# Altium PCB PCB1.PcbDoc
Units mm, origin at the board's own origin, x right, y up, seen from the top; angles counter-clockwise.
Board outline 30.4 x 31.22 mm, 2 copper layers (Top Layer, Bottom Layer); 47 components, 33 nets, 158 pads, 154 vias.
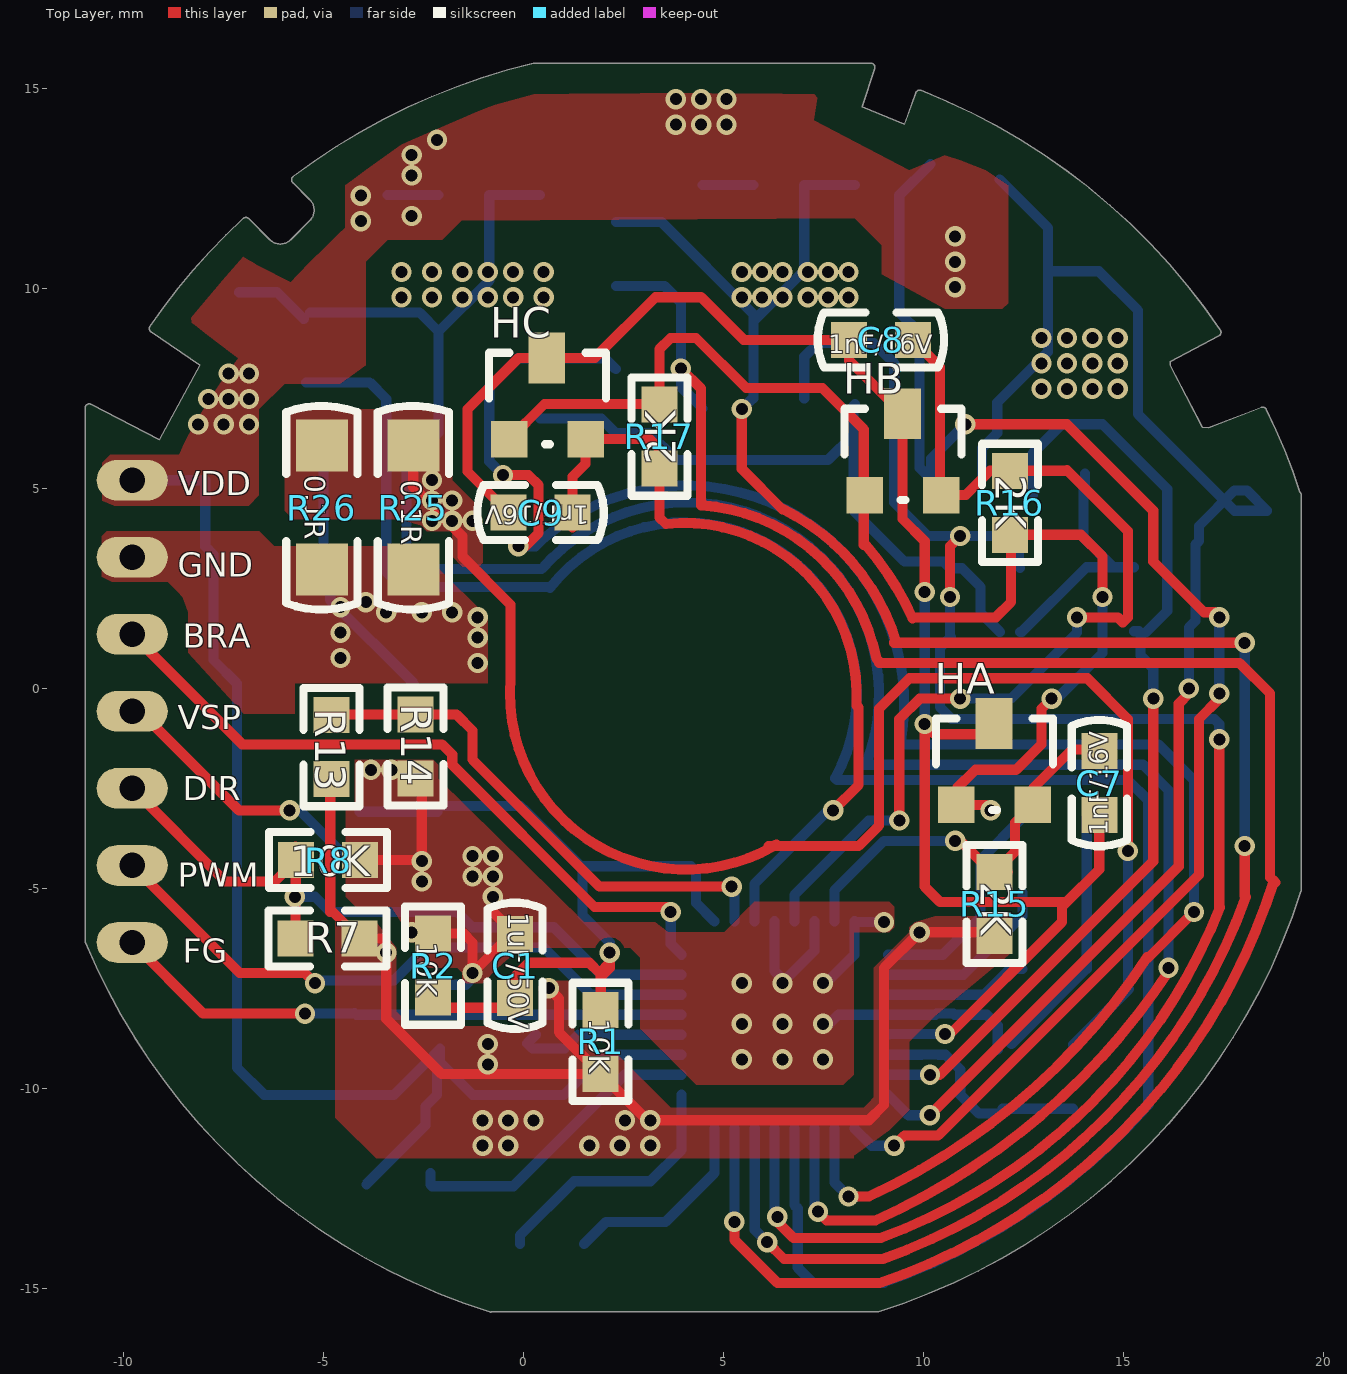
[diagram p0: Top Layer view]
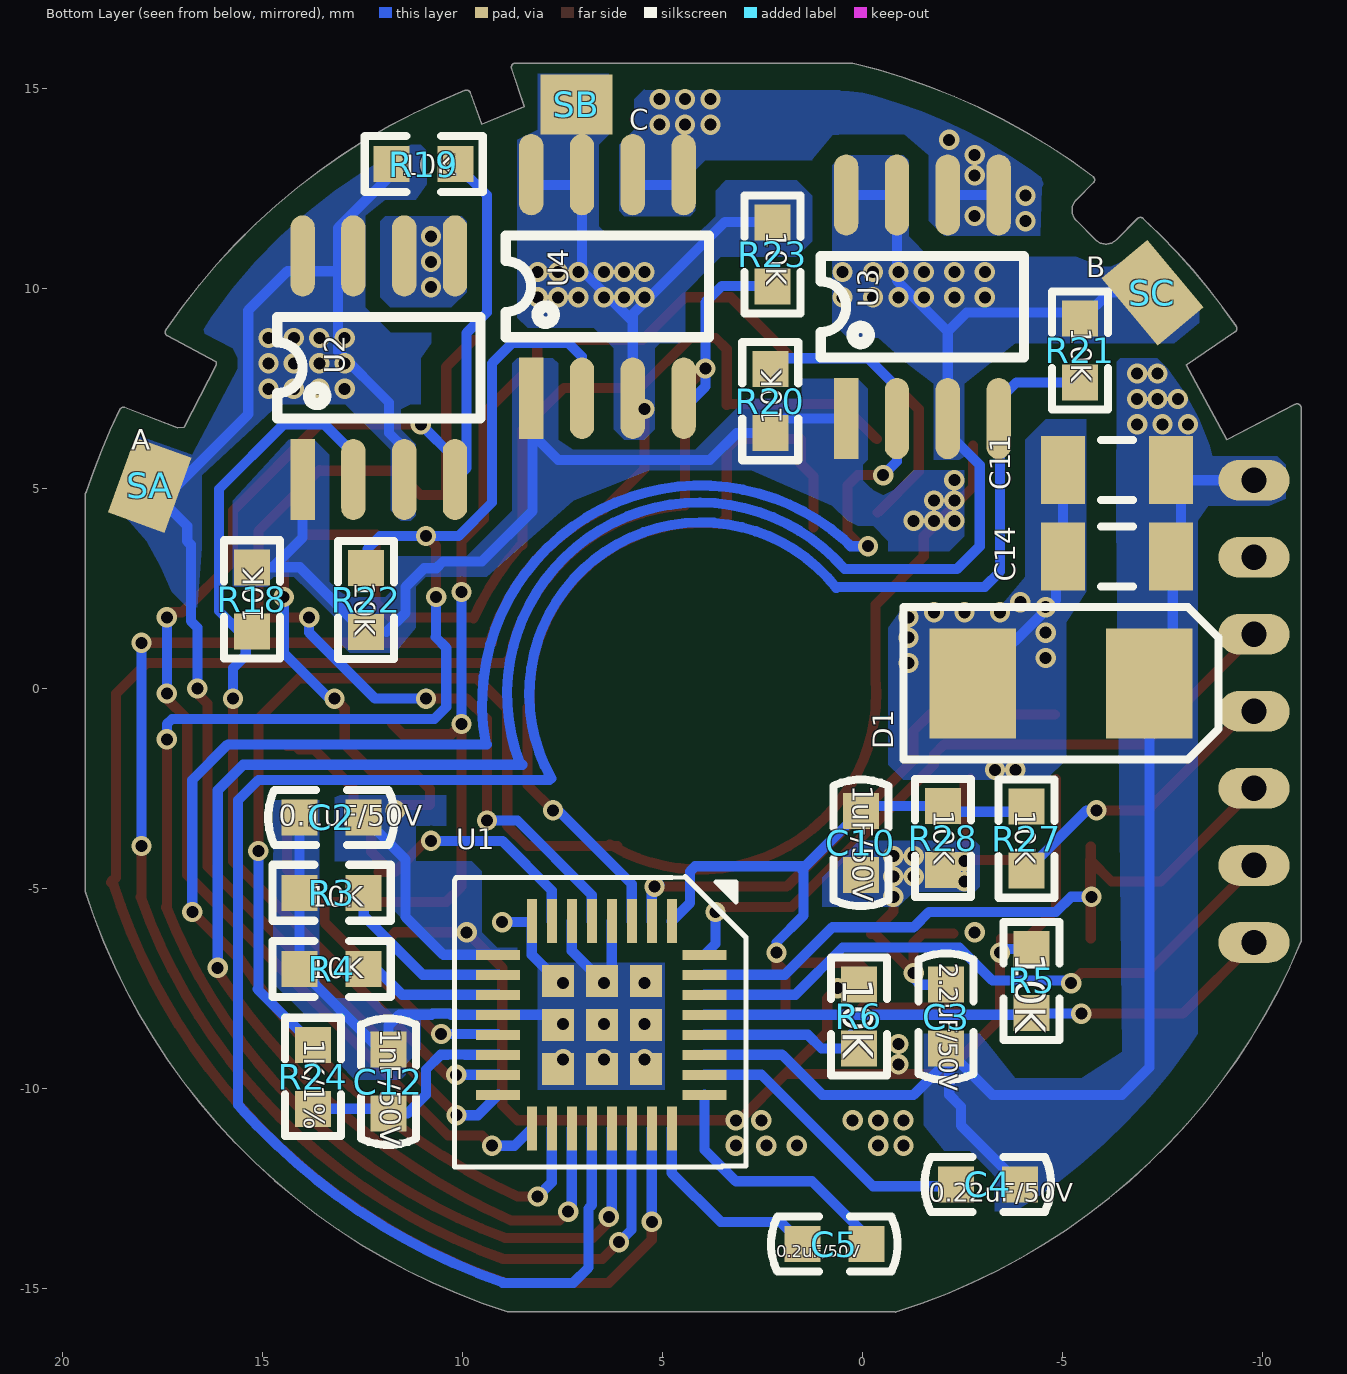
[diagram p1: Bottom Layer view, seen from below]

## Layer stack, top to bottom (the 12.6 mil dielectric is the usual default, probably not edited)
Top Solder: solder mask 0.0102, Solder Resist, Dk 3.5
Top Layer: signal copper 0.0356
Dielectric 1: dielectric 0.32, FR-4, Dk 4.8
Bottom Layer: signal copper 0.0356
Bottom Solder: solder mask 0.0102, Solder Resist, Dk 3.5

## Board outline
-10.95,-6.341 cw(c-10.855,-6.302) -10.957,-6.302 -10.957,7.013 cw(c-10.855,7.013) -10.808,7.104 -10.809,7.104 -10.808,7.104 -9.097,6.22 -8.084,8.083 -9.308,8.915 cw(c-9.251,8.999) -9.335,9.057 cw(c4.013,-0.127) -7.007,11.75 cw(c-6.938,11.675) -6.86,11.741 -6.338,11.219 ccw(c-6.41,11.147) -6.338,11.219 ccw(c-6.077,11.479) -5.817,11.219 -5.338,11.698 ccw(c-5.266,11.626) -5.338,11.698 ccw(c-5.598,11.958) -5.23,11.958 ccw(c-5.598,11.958) -5.338,12.218 cw(c-5.266,12.291) -5.338,12.219 -5.338,12.218 -5.765,12.646 cw(c-5.693,12.718) -5.755,12.799 cw(c4.013,-0.127) 0.255,15.633 cw(c0.279,15.534) 0.298,15.634 8.687,15.634 cw(c8.687,15.532) 8.789,15.532 cw(c8.687,15.532) 8.784,15.5 8.47,14.548 9.529,14.106 9.809,14.89 cw(c9.905,14.856) 9.943,14.951 cw(c4.013,-0.127) 17.425,8.964 cw(c17.34,8.906) 17.442,8.906 cw(c17.34,8.906) 17.388,8.816 16.167,8.168 16.167,8.089 16.969,6.535 17.131,6.517 18.447,7.025 cw(c18.484,6.93) 18.576,6.975 cw(c4.013,-0.127) 19.413,4.908 cw(c19.343,4.834) 19.445,4.834 19.445,-5.047 ccw(c19.343,-5.047) 19.445,-5.045 19.445,-5.047 cw(c19.343,-5.047) 19.44,-5.078 cw(c4.013,-0.127) 8.881,-15.58 cw(c8.85,-15.483) 8.85,-15.585 -0.789,-15.585 cw(c-0.814,-15.486) -0.844,-15.584 cw(c4.013,-0.127)

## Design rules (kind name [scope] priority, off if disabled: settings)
Clearance [All] p1: gap=0.127
PolygonConnect [All] p1: connectstyle=Direct reliefconductorwidth=0.254 reliefentries=4 polygonreliefangle="90 Angle" airgapwidth=0.254
RoutingVias [All] p1: holewidth=0.711 width=1.27 viastyle="Through Hole" minholewidth=0.711 minwidth=1.27 maxholewidth=0.711 maxwidth=1.27
SilkToSilkClearance [All] p1: silktosilkclearance=0.051
SolderMaskExpansion [All] p1: expansion=0.102
Width [All] p1: maxlimit=0.254 minlimit=0.254 preferedwidth=0.254
29 further rules are at their usual default settings.

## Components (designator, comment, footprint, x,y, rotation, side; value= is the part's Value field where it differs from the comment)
C1 "1uF/50V" C0603 -3.302,-7.239 r180 top
C2 "0.1uF/50V" C0603 13.589,-0.127 r90 bottom
C3 "2.2uF/50V" C0603 1.016,-8.509 r0 bottom
C4 "0.22uF/50V" C0603 -3.429,-15.494 r270 bottom
C5 "0.2uF/50V" C0603 1.016,-10.795 r90 bottom
C7 "1nF/16V" C0603 11.303,-2.667 r180 top
C8 "1nF/16V" C0603 8.636,11.811 r90 top
C9 "1nF/16V" C0603 0.127,7.493 r90 top
C10 "1uF/50V" C0603 -3.048,-3.556 r180 bottom
C11 "22uF/25V" C1206 -6.35,5.461 r180 bottom
C12 "1nF/50V" C0603 8.763,-9.525 r180 bottom
C14 "22uF/25V" C1206 -6.35,3.302 r180 bottom
D1 "24V/Zener" SMB -4.953,0.127 r180 bottom
HA "HALL_SOT23-3" SOT-23 15.113,-2.54 r0 top locked
HB "HALL_SOT23-3" SOT-23 12.827,5.207 r0 top locked
HC "HALL_SOT23-3" SOT-23 3.937,6.604 r0 top locked
R1 "10K" R0603 0.254,-10.287 r180 top
R2 "10K" R0603 -3.937,-8.382 r180 top
R3 "10K" R0603 14.732,-3.429 r90 bottom
R4 "10K" R0603 14.732,-5.334 r90 bottom
R5 "10K" R0603 -2.54,-8.763 r0 bottom
R6 "10K" R0603 1.778,-9.652 r0 bottom
R7 "" R0603 -6.35,-4.572 r90 top
R8 "10K" R0603 -3.429,-5.969 r270 top
R13 "" R0603 -6.477,-2.921 r180 top
R14 "" R0603 -1.016,0 r0 top
R15 "2K" R0603 13.462,-3.937 r0 top
R16 "2K" R0603 13.843,6.096 r0 top
R17 "2K" R0603 5.08,7.747 r0 top
R18 "10K" R0603 13.589,3.683 r180 bottom
R19 "10K" R0603 9.525,11.43 r270 bottom
R20 "10K" R0603 0.635,8.636 r180 bottom
R21 "10K" R0603 -7.112,9.906 r180 bottom
R22 "10K" R0603 14.097,0.762 r0 bottom
R23 "10K" R0603 3.937,9.398 r0 bottom
R24 "1K/1%" R0603 12.065,-8.255 r180 bottom
R25 "0.1R" R1206 -0.508,4.445 r0 top
R26 "0.1R" R1206 -2.794,4.445 r0 top
R27 "10K" R0603 -2.413,-5.207 r0 bottom
R28 "10K" R0603 -3.683,-2.286 r180 bottom
SA "" cp1#1 23.749,7.239 r20 top
SB "" cp1#2 13.462,14.605 r0 top
SC "" cp1#3 -2.413,5.842 r320 top
U1 "SDC9270_QFN32" "QFN32 (5*5)" 6.604,-3.175 r270 bottom
U2 "MOS" SOP-8 17.907,7.874 r0 bottom
U3 "MOS" SOP-8 4.318,9.398 r0 bottom
U4 "MOS" SOP-8 12.192,9.906 r0 bottom

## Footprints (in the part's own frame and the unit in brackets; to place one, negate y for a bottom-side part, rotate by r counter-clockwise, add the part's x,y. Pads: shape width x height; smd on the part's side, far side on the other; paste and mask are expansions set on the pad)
C0603 [mm]
  rect 0.9x0.9 smd: 1(-3.096,0.496) 2(-3.096,-1.104)
  silkscreen extent -3.78,-1.88 -2.41,1.28
C1206 [mm] "Chip Capacitor, Body 3.2x1.6mm, IPC High Density"
  rect 1.1x1.7 smd: 1(-1.35,0) 2(1.35,0)
  silkscreen extent -0.4,-0.75 0.4,0.75, body extent -1.7,-0.9 1.7,0.9, height 1.3
cp1#1 [mm]
  rect 1.5x2 smd far side: 1(-6.3,0)
cp1#2 [mm]
  rect 1.8x1.5 smd far side: 1(-6.3,0)
cp1#3 [mm]
  rect 1.5x2.2 smd far side: 1(-6.3,0)
"QFN32 (5*5)" [mm]
  rect 1.1x0.25 smd: 1(2.643,1.828) 2(2.643,1.328) 3(2.643,0.828) 4(2.643,0.328) 5(2.643,-0.172) 6(2.643,-0.672) 7(2.643,-1.172) 8(2.643,-1.672) 17(7.823,-1.672) 18(7.823,-1.172) 19(7.823,-0.672) 20(7.823,-0.172) 21(7.823,0.328) 22(7.823,0.828) 23(7.823,1.328) 24(7.823,1.828)
  rect 0.25x1.1 smd: 9(3.483,-2.512) 10(3.983,-2.512) 11(4.483,-2.512) 12(4.983,-2.512) 13(5.483,-2.512) 14(5.983,-2.512) 15(6.483,-2.512) 16(6.983,-2.512) 25(6.983,2.648) 26(6.483,2.648) 27(5.983,2.648) 28(5.483,2.648) 29(4.983,2.648) 30(4.483,2.648) 31(3.983,2.648) 32(3.483,2.648)
  rect 0.8x0.8 smd: 33(4.133,-1.022) 33(4.133,0.078) 33(4.133,1.178) 33(5.233,-1.022) 33(5.233,0.078) 33(5.233,1.178) 33(6.333,-1.022) 33(6.333,0.078) 33(6.333,1.178)
  silkscreen extent 1.52,-3.6 8.79,3.68
R0603 [mm]
  rect 0.9x0.9 smd: 1(-1.679,-0.653) 2(-1.679,-2.253)
  silkscreen extent -2.38,-2.93 -0.98,0.02
R1206 [mm]
  rect 1.3x1.3 smd: 1(-2.244,-1.475) 2(-2.244,1.625)
  silkscreen extent -3.13,-2.47 -1.35,2.62
SMB [mm]
  rect 2.159x2.743 smd: 1(-2.21,0) 2(2.21,0)
  silkscreen extent -3.94,-1.91 3.94,1.91
SOP-8 [mil]
  rect 24x80 smd: 1(-153.56,104.3)
  oval 24x80 smd: 2(-203.56,104.3) 3(-253.56,104.3) 4(-303.56,104.3) 5(-303.56,-115.7) 6(-253.56,-115.7) 7(-203.56,-115.7) 8(-153.56,-115.7)
  silkscreen extent -329,-56 -129,44
SOT-23 [mil]
  rect 36x36 smd: 1(-93.79,-14.61) 3(-168.79,-14.61)
  rect 36x50 smd: 2(-131.79,65.39)
  silkscreen extent -189,-20 -74,70

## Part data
C1 C7 C8 C9 C10 C11 C12 C14: library part C0603, "C0603"
C2 C4 C5: library part C0805, "C0805"
C3: library part C1206, "C1206"
D1: library part Zener_SOD-123, "Zener Diode"
R1 R2 R3 R4 R5 R6 R7 R8 R13 R14 R15 R16 R17 R24 R27 R28: library part R0603, "R0603"
R18 R19 R20 R21 R22 R23: library part R1_0603
R25 R26: library part R2512
SA SB SC: library part CON1, "Connector"

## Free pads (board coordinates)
  oval 1.778x1.016 hole 0.635: 1(-9.779,-6.35) 1(-9.779,-4.424) 1(-9.779,-2.498) 1(-9.779,-0.572) 1(-9.779,1.355) 1(-9.779,3.281) 1(-9.779,5.207)

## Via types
v1: diameter 0.508, hole 0.3, Top Layer to Bottom Layer, 154 vias

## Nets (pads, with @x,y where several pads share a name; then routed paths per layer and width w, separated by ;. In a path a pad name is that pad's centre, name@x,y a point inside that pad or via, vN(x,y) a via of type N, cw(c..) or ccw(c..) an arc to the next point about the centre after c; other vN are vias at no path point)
BRAKE: pad.1@-9.779,1.355 U1.32 | length 17.7
  Top Layer w0.254: pad.1@-9.779,1.355 -7.027,-1.397 -2.032,-1.397 -1.778,-1.651 -1.778,-1.905 1.778,-5.461 3.683,-5.461 v1(3.683,-5.588)
  Bottom Layer w0.254: v1(3.683,-5.588) 3.683,-6.385 U1.32
CP1: C5.1 U1.24 | length 5.1
  Bottom Layer w0.254: C5.1 2.068,-13.335 3.556,-13.335 4.776,-12.115 U1.24
CP2: C5.2 U1.25 | length 6.5
  Bottom Layer w0.254: C5.2 -0.088,-13.677 1.27,-12.319 3.175,-12.319 3.956,-11.538 U1.25
DIR: pad.1@-9.779,-2.498 R7.1 R8.2 U1.31 | length 19
  Top Layer w0.254: pad.1@-9.779,-2.498 -7.451,-4.826 -6.218,-4.826 R8.2@-5.697,-4.305 ; v1(-5.715,-5.207) -5.682,-5.174 R8.2 R8.2@-5.697,-4.305 ; R7.1 R8.2@-5.697,-4.305 ; R8.2@-5.697,-3.955 R8.2@-5.697,-4.305
  Bottom Layer w0.254: v1(-5.715,-5.207) -5.207,-5.207 -4.826,-5.588 -1.651,-5.588 -1.27,-5.969 0.762,-5.969 1.951,-7.158 U1.31
FG: pad.1@-9.779,-6.35 R5.1 U1.29 | length 14.5
  Top Layer w0.254: pad.1@-9.779,-6.35 -8.001,-8.128 v1(-5.461,-8.128)
  Bottom Layer w0.254: v1(-5.461,-8.128) -4.237,-8.128 R5.1 -4.171,-8.158 U1.29
GHA: R19.1 U1.17 U2.4 | length 37.6
  Top Layer w0.254: v1(9.271,-11.43) 9.525,-11.176 10.37,-11.176 16.891,-4.655 16.891,-0.762 17.399,-0.254 v1(17.399,-0.127) ; v1(11.049,6.604) 13.589,6.604 15.748,4.445 15.748,3.175 17.018,1.905 17.272,1.905 v1(17.399,1.778)
  Bottom Layer w0.254: U1.17 8.708,-11.43 v1(9.271,-11.43) ; R19.1 9.398,12.329 9.398,9.398 9.906,8.89 9.906,5.515 U2.4 10.196,5.751 v1(11.049,6.604) ; v1(17.399,-0.127) v1(17.399,1.778)
GHB: R21.2 U1.20 U3.4 | length 53
  Bottom Layer w0.254: R21.2 -3.843,7.653 -3.429,7.239 -3.429,2.921 -3.048,2.54 0.635,2.54 ; 0.664,2.517 cw(c4.039,-0.147) 7.79,-2.249 ; U1.20 6.776,-12.916 6.858,-12.998 6.858,-14.478 7.239,-14.859 9.012,-14.859 ; 7.794,-2.241 7.839,-2.286 15.113,-2.286 15.621,-2.794 15.621,-10.414 ; 9.012,-14.844 ccw(c3.891,-0.081) 15.563,-10.47
GHC: R23.1 U1.23 U4.4 | length 51
  Top Layer w0.254: v1(3.937,8.001) 4.445,7.493 4.445,4.583 ; 4.446,4.582 cw(c4.121,-0.208) 8.826,0.749 8.89,0.685 8.89,0.635 17.907,0.635 18.669,-0.127 18.669,-4.725 18.796,-4.852 ; v1(5.276,-13.335) 5.276,-13.785 6.35,-14.859 8.89,-14.859 ; 8.892,-14.865 ccw(c3.937,-0.127) 18.766,-4.803
  Bottom Layer w0.254: R23.1@2.314,10.066 3.523,10.066 3.937,9.652 v1(3.937,8.001) 3.937,7.547 U4.4@4.481,7.003 ; v1(5.276,-13.335) U1.23
GLA: R18.2 U1.15 U2.2 | length 24
  Top Layer w0.254: v1(10.166,-9.658) 10.408,-9.658 15.748,-4.318 v1(15.748,-0.254)
  Bottom Layer w0.254: U1.15 v1(10.166,-9.658) ; U2.2@12.736,4.844 12.736,5.878 13.462,6.604 14.478,6.604 16.096,4.986 16.096,1.938 R18.2@15.555,1.397 ; R18.2 R18.2@15.395,1.43 ; R18.2@15.428,1.397 15.428,0.828 15.748,0.508 v1(15.748,-0.254)
GLB: R20.1 U1.18 U3.2 | length 47.2
  Top Layer w0.254: v1(-0.508,5.334) 0.127,5.334 0.381,5.08 0.381,3.888 0.049,3.556 v1(-0.127,3.556) ; v1(8.128,-12.7) 8.636,-12.7 ccw(c1.579,2.559) 15.599,-6.719 ; 15.616,-6.736 v1(16.764,-5.588)
  Bottom Layer w0.254: v1(-0.508,5.334) -0.853,5.679 U3.2 -0.853,7.529 -0.127,8.255 2.042,8.255 R20.1 ; v1(-0.127,3.556) 0.303,3.556 0.472,3.724 cw(c4.064,-0.381) 9.437,-1.321 ; U1.18 7.776,-12.348 v1(8.128,-12.7) ; 9.398,-1.397 15.875,-1.397 16.764,-2.286 v1(16.764,-5.588)
GLC: R22.2 U1.21 U4.2 | length 44.7
  Top Layer w0.254: v1(6.35,-13.208) 6.35,-13.335 6.75,-13.735 8.944,-13.735 ccw(c3.937,-0.127) 17.417,-5.468 17.399,-5.45 v1(17.399,-1.27) ; v1(10.668,2.286) 10.668,3.556 v1(10.922,3.81)
  Bottom Layer w0.254: v1@6.276,-13.134 U1.21 ; U4.2 7.021,8.291 7.366,8.636 8.763,8.636 9.271,8.128 9.271,4.649 10.11,3.81 v1(10.922,3.81) 12.065,3.81 12.385,3.49 12.385,3.048 R22.2 ; v1(10.668,2.286) 10.668,1.303 10.684,1.286 10.414,1.016 10.414,-0.464 10.712,-0.762 17.272,-0.762 17.399,-0.889 v1(17.399,-1.27)
GND: 
HA: C9.2 HC.1 R17.2 U1.3 | length 20.5
  Top Layer w0.254: C9.2@1.231,4.025 C9.2 1.231,5.295 1.555,5.619 HC.1 3.165,6.233 3.401,5.997 R17.2 3.401,4.276 3.565,4.112 cw(c4.034,-0.162) 8.326,-0.421 8.382,-0.477 8.382,-2.413 v1(7.747,-3.048)
  Bottom Layer w0.254: U1.3 5.776,-4.887 7.747,-2.916 v1(7.747,-3.048)
HB: C8.2 HB.1 R16.1 U1.5 | length 25.7
  Top Layer w0.254: v1(9.398,-3.302) 9.398,-0.762 9.906,-0.254 v1(10.922,-0.254) ; C8.2 10.414,8.041 HB.1@10.414,4.867 ; HB.1 11.059,4.836 11.666,5.443 R16.1 13.571,5.443 13.589,5.461 15.113,3.937 15.113,1.778 14.986,1.651 14.859,1.778 v1(13.843,1.778)
  Bottom Layer w0.254: U1.5 6.776,-5.162 8.636,-3.302 v1(9.398,-3.302) ; v1@10.922,-0.127 v1(10.922,-0.254) 12.192,-0.254 13.843,1.397 v1(13.843,1.778)
HC: C7.2 HA.1 R15.1 U1.7 | length 10.5
  Top Layer w0.254: v1(10.795,-3.81) 10.922,-3.81 11.702,-4.59 R15.1@12.108,-4.59 ; R15.1 12.291,-4.082 12.291,-3.351 HA.1 12.731,-2.509 13.716,-1.524 14.097,-1.524 14.185,-1.436 C7.2@14.399,-1.436
  Bottom Layer w0.254: U1.7 7.776,-5.051 9.017,-3.81 v1(10.795,-3.81)
ILIMIT: C12.2 R24.2 U1.14 | length 5.5
  Bottom Layer w0.254: U1.14 9.948,-9.158 9.956,-9.15 10.377,-9.15 10.385,-9.158 10.555,-9.158 10.922,-9.525 10.922,-10.16 11.391,-10.629 C12.2 ; C12.2@11.979,-10.508 R24.2
ISENSE: R18.1 R20.2 R22.1 R24.1 R25.2 R26.2 U2.1 U3.1 U4.1 | length 61.1
  Top Layer w0.254: R25.2 -2.752,5.038 -1.524,3.81 -1.524,3.302 -0.319,2.097 -0.319,0.254 ccw(c4.064,-0.127) 6.265,-3.937 ccw(c4.064,-0.127) 6.328,-3.9 ; 6.135,-3.937 8.382,-3.937 8.89,-3.429 8.89,-0.508 9.652,0.254 14.097,0.254 15.113,-0.762 v1(15.113,-4.064)
  Bottom Layer w0.254: U3.1 1.948,6.749 R20.2 3.154,6.383 3.822,5.715 7.62,5.715 U4.1@8.255,6.35 ; U4.1@8.291,7.112 8.255,7.076 U4.1@8.255,6.35 ; 11.91,1.415 11.43,1.895 11.43,2.54 10.965,3.005 10.667,3.005 10.497,3.175 9.525,3.175 8.255,4.445 U4.1@8.255,6.35 ; R22.1 12.464,1.415 14.079,3.03 14.75,3.03 ; R24.1 15.136,-7.516 15.113,-7.493 v1(15.113,-4.064) ; U2.1 14.006,3.774 14.75,3.03 ; U2.1@14.043,4.88 U2.1@14.043,5.37 ; R18.1 14.75,3.03
  other v1: -2.286,4.191 -1.778,4.191 -1.27,4.191 -2.286,4.699 -1.778,4.699 -2.286,5.207
LEAD: R13.2 R14.1 U1.2 | length 13.5
  Top Layer w0.254: R13.2@-4.798,-0.653 R14.1 -1.669,-0.653 -1.27,-1.052 -1.27,-1.778 1.905,-4.953 v1(5.207,-4.953)
  Bottom Layer w0.254: v1(5.207,-4.953) 5.207,-4.87 5.163,-4.826 5.08,-4.909 5.276,-5.105 U1.2
MODE: R3.2 U1.10 | length 4.5
  Bottom Layer w0.254: U1.10 11.003,-7.158 12.479,-5.682 R3.2
NetP1_3: pad.1@-9.779,-0.572 R27.1 | length 7.3
  Top Layer w0.254: pad.1@-9.779,-0.572 -9.588,-0.572 -7.112,-3.048 v1(-5.842,-3.048)
  Bottom Layer w0.254: v1(-5.842,-3.048) -5.598,-3.048 R27.1
NFLT: R6.1 U1.28 | length 4.4
  Bottom Layer w0.254: R6.1@0.313,-8.658 0.099,-8.872 0.226,-8.999 1.034,-8.999 1.375,-8.658 U1.28
PGND: C7.1 C8.1 C9.1 HA.2 HB.2 HC.2 U1.13 | length 43
  Top Layer w0.254: C9.1 -1.397,5.425 -1.397,6.985 -0.117,8.265 HC.2 1.788,8.265 3.302,9.779 4.445,9.779 5.509,8.715 C8.1 8.14,8.208 HB.2 9.479,4.237 10.033,3.683 v1(10.033,2.413) ; v1(10.541,-8.636) 10.668,-8.636 13.462,-5.842 13.462,-5.461 13.589,-5.334 ; HA.2 11.502,-1.143 10.287,-1.143 v1(10.033,-0.889) 10.033,-4.953 10.414,-5.334 13.589,-5.334 ; C7.1@14.399,-3.036 14.399,-4.524 13.589,-5.334
  Bottom Layer w0.254: U1.13 9.138,-8.636 v1(10.541,-8.636) ; v1(10.033,-0.889) v1(10.033,2.413)
PWM: pad.1@-9.779,-4.424 U1.30 | length 15.8
  Top Layer w0.254: pad.1@-9.779,-4.445 -9.779,-4.424 -7.091,-7.112 -5.461,-7.112 v1(-5.207,-7.366)
  Bottom Layer w0.254: v1(-5.207,-7.366) -5.142,-7.301 -3.237,-7.301 -2.413,-6.477 0.508,-6.477 1.689,-7.658 U1.30
PWMIN: 
SA: R19.2 SA.1 U1.16 U2.3 U2.7 U2.8 | length 39.2
  Top Layer w0.254: v1(10.16,-10.668) 16.383,-4.445 16.383,-0.381 16.637,-0.127 v1(16.637,0)
  Bottom Layer w0.254: U1.16 9.626,-10.668 v1(10.16,-10.668) ; U2.3 11.466,6.005 11.847,6.386 11.847,7.148 13.117,8.418 13.117,10.432 ; R19.2@11.905,12.728 13.117,11.516 13.117,10.432 ; v1(16.637,0) 16.637,1.524 16.8,1.687 16.8,3.592 16.891,3.683 16.891,4.064 17.78,4.953 18.084,4.953 18.592,4.445 17.78,4.445 15.367,6.858 15.367,9.452 14.387,10.432 13.117,10.432
  other v1: 12.954,7.493 13.589,7.493 14.224,7.493 14.859,7.493 12.954,8.128 13.589,8.128 14.224,8.128 14.859,8.128 12.954,8.763 13.589,8.763 14.224,8.763 14.859,8.763
SB: R21.1 SC.1 U1.19 U3.3 U3.7 U3.8 | length 59.1
  Top Layer w0.254: v1(7.366,-13.081) 7.587,-13.302 8.798,-13.302 ccw(c1.7,2.497) v1@16.176,-7.012
  Bottom Layer w0.254: SC.1@-7.112,9.906 -6.157,9.906 R21.1@-5.489,9.238 ; R21.1@-5.329,9.398 -2.594,9.398 -2.123,8.926 ; U3.8 U3.7 -0.853,10.196 -2.123,8.926 ; U1.19 7.276,-12.991 v1(7.366,-13.081) ; 8.509,-1.905 15.494,-1.905 16.129,-2.54 v1(16.129,-6.985) ; 8.572,-1.88 ccw(c4.093,-0.152) 0.456,2.983 -2.348,2.983 -2.921,3.556 -2.921,5.588 -2.123,6.386 U3.3 -2.123,8.926
  other v1: -3.048,9.779 -2.286,9.779 -1.524,9.779 -0.889,9.779 -0.254,9.779 0.508,9.779 -3.048,10.414 -2.286,10.414 -1.524,10.414 -0.889,10.414 -0.254,10.414 0.508,10.414
SC: R23.2 SB.1 U1.22 U4.3 U4.7 U4.8 | length 54
  Top Layer w0.254: v1(5.461,6.985) 5.461,5.492 6.48,4.473 ; v1(6.096,-13.843) 6.516,-14.263 8.985,-14.263 ccw(c3.937,-0.127) 18.058,-5.216 18.034,-5.191 v1(18.034,-3.937) ; 6.488,4.482 cw(c4.1,-0.422) 9.326,1.143 ; 9.271,1.143 v1(18.034,1.143)
  Bottom Layer w0.254: R23.2@2.314,11.666 3.447,11.666 5.751,9.362 5.751,9.18 ; v1(5.461,6.985) 5.733,7.257 U4.3 5.751,9.18 ; U1.22 5.784,-11.006 5.784,-13.531 v1(6.096,-13.843) ; U4.8@8.291,12.591 7.021,12.591 7.021,10.45 5.751,9.18 ; v1(18.034,-3.937) v1(18.034,1.143)
  other v1: 5.461,9.779 5.969,9.779 6.477,9.779 7.112,9.779 7.62,9.779 8.128,9.779 5.461,10.414 5.969,10.414 6.477,10.414 7.112,10.414 7.62,10.414 8.128,10.414
SGND: C1.2 C2.1 C3.2 C10.2 C11.1 C12.1 C14.1 D1.1 pad.1@-9.779,3.281 R2.2 R3.1 R4.1 R8.1 R14.2 R25.1 R26.1 R28.2 U1.4 U1.6 U1.8 U1.12 U1.33 | length 33
  Top Layer w0.254: R8.1 -2.568,-4.29 v1(-2.54,-4.318) -2.54,-2.408 R14.2 ; R2.2 -1.491,-6.129 -1.27,-6.35 v1(-1.27,-7.112) -0.293,-6.135 C1.2 -0.762,-5.58 v1(-0.762,-5.207)
  Bottom Layer w0.254: C11.1 C14.1 -4.826,3.128 -4.826,2.21 D1.1 ; C3.2 -1.436,-7.405 -1.27,-7.239 v1(-1.27,-7.112) ; U1.4 6.276,-7.058 6.526,-7.308 7.276,-6.558 U1.6 ; U1.33@7.626,-8.408 7.876,-8.158 U1.12 10.3,-8.158 10.331,-8.128 10.751,-8.128 10.782,-8.158 11.587,-8.158 11.859,-8.43 C12.1 ; U1.33@7.626,-7.308 8.276,-6.658 U1.8 8.3,-5.842 v1(9.017,-5.842) ; C12.1@12.09,-8.788 12.1,-8.788 12.202,-8.89 R4.1 ; R4.1@14.085,-7.007 C2.1
  other v1: 5.461,-9.271 6.477,-9.271 7.493,-9.271 5.461,-8.382 6.477,-8.382 7.493,-8.382 5.461,-7.366 6.477,-7.366 7.493,-7.366 -2.794,-6.096 -2.54,-4.826 -1.27,-4.699 -0.762,-4.699 -1.27,-4.191 -0.762,-4.191 -3.81,-2.032 -3.302,-2.032 -1.143,0.635 -4.572,0.762 -1.143,1.27 -4.572,1.397 -1.143,1.778 -3.429,1.905 -2.54,1.905 -1.778,1.905 -4.572,2.032 -3.937,2.159
SREF: C1.1 C10.1 R1.2 R2.1 R27.2 R28.1 U1.1 | length 20.3
  Top Layer w0.254: R2.1@-2.385,-7.983 C1.1@0.018,-7.983 ; C1.1 -0.206,-7.191 0.127,-6.858 1.651,-6.858 1.905,-7.112 2.159,-6.858 v1(2.159,-6.604) 2.159,-6.985 1.933,-7.211 R1.2
  Bottom Layer w0.254: R27.2@-4.092,-3.081 R28.1@-2.146,-3.081 ; R28.1 -0.073,-2.939 C10.1 1.524,-4.536 ; v1(2.159,-6.604) 2.159,-6.35 1.48,-5.671 1.48,-4.445 4.191,-4.445 4.318,-4.572 4.318,-5.36 U1.1
TEST: R4.2 U1.11 | length 3.6
  Bottom Layer w0.254: U1.11 11.519,-7.658 12.164,-7.013 R4.2
VCP: C4.2 U1.26 | length 7.7
  Bottom Layer w0.254: C4.2@-2.325,-12.113 C4.2 -2.278,-12.446 -0.254,-12.446 2.534,-9.658 U1.26
VDD: C3.1 C4.1 C11.2 C14.2 D1.2 pad.1@-9.779,5.207 U1.27 U2.5 U2.6 U3.5 U3.6 U4.5 U4.6 | length 36.4
  Bottom Layer w0.254: pad.1@-9.779,5.207 -7.954,5.207 -7.954,3.556 -7.747,3.349 -7.747,0.711 D1.2 -7.163,-9.474 -6.477,-10.16 -3.234,-10.16 C3.1@-2.159,-9.085 ; C4.1 -2.449,-10.922 -2.449,-10.45 -2.159,-10.16 C3.1@-2.159,-9.085 ; U3.5 U3.6 ; U1.27 2.018,-9.158 1.016,-10.16 -1.27,-10.16 -2.08,-9.35 C3.1 C3.1@-2.159,-9.085 ; U4.5@4.481,12.591 U4.6@5.751,12.591
  other v1: -8.128,6.604 -7.493,6.604 -6.858,6.604 -7.874,7.239 -7.366,7.239 -6.858,7.239 -7.366,7.874 -6.858,7.874 10.795,10.033 10.795,10.668 10.795,11.303 -4.064,11.684 -2.794,11.811 -4.064,12.319 -2.794,12.827 -2.794,13.335 -2.159,13.716 3.81,14.097 4.445,14.097 5.08,14.097 3.81,14.732 4.445,14.732 5.08,14.732
VREF: C2.2 HA.3 HB.3 HC.3 R1.1 R5.2 R6.2 R7.2 R13.1 R15.2 R16.2 R17.1 U1.9 | length 69.3
  Top Layer w0.254: R13.1@-4.826,-2.268 -4.826,-5.588 -4.76,-5.588 R7.2 -3.457,-6.251 -3.457,-6.576 v1(-3.429,-6.604) -3.429,-8.255 -2.05,-9.634 R1.1 ; HC.3 0.529,7.112 R17.1@3.401,7.112 ; v1(0.635,-7.493) 0.889,-7.747 0.889,-8.59 R1.1 ; R17.1 R17.1@3.401,7.112 ; 8.509,3.584 8.509,6.477 7.475,7.511 5.57,7.511 4.318,8.763 3.683,8.763 3.401,8.481 R17.1@3.401,7.112 ; 8.562,3.584 cw(c2.794,-1.397) 9.732,1.757 ; 9.732,1.778 11.811,1.778 12.192,2.159 12.192,3.815 R16.2 13.937,3.843 14.478,3.302 v1(14.478,2.286) ; v1(11.684,-3.048) 11.547,-2.911 HA.3 10.826,-2.509 11.303,-2.032 12.319,-2.032 12.954,-1.397 12.954,-0.508 v1(13.208,-0.254) ; R15.2 11.689,-6.096 v1(9.906,-6.096) 9.017,-6.985 9.017,-10.414 8.636,-10.795 3.094,-10.795 R1.1
  Bottom Layer w0.254: R5.2 -3.523,-6.51 v1(-3.429,-6.604) ; U1.9 10.487,-6.658 11.43,-5.715 11.43,-4.278 C2.2 ; v1(13.208,-0.254) 13.335,-0.254 14.478,0.889 v1(14.478,2.286)
  other v1: -1.016,-11.43 -0.381,-11.43 1.651,-11.43 2.413,-11.43 3.175,-11.43 -1.016,-10.795 -0.381,-10.795 0.254,-10.795 2.54,-10.795 3.175,-10.795 -0.889,-9.398 -0.889,-8.89

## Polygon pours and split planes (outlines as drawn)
VDD on Bottom Layer "VDD" (solid, remove dead copper, pour order 46): -8.763,5.715 -6.223,5.842 -6.223,5.945 -6.35,5.818 -6.35,8.255 -7.366,8.255 ccw(c-3.098,4.253)
VDD on Bottom Layer "VDD" (solid, remove dead copper, pour order 44): -8.372,-8.636 ccw(c4.172,-0.305) -3.81,-13.074 -3.299,-13.074 -3.299,-12.189 -3.157,-12.047 -2.921,-11.811 -2.667,-11.557 -2.54,-11.557 -2.032,-11.557 -1.524,-10.922 -1.524,-8.636 -2.921,-8.636 -3.81,-9.742 -5.461,-9.742 -6.483,-9.087 -6.338,4.191 -6.338,5.969 -8.681,5.969 -8.681,5.804 -10.363,5.804 -10.572,5.594 -10.572,4.744 -10.16,4.572 -8.636,4.572 -8.372,4.191
SGND on Bottom Layer "SGND" (solid, remove dead copper, pour order 35): 14.351,-2.794 14.735,-2.794 14.735,-7.366 13.846,-8.255 13.208,-8.255 13.081,-8.382 13.081,-9.398 12.7,-9.779 11.557,-9.779 11.43,-9.652 11.43,-9.398 11.303,-9.271 11.049,-9.017 11.049,-8.255 11.049,-8.382 10.922,-8.255 10.16,-8.255 10.033,-8.255 10.033,-8.001 10.414,-8.001 10.795,-8.001 11.303,-8.001 11.938,-8.001 12.192,-7.747 13.208,-7.747 13.589,-7.366 13.589,-3.302 13.589,-2.794
VDD on Bottom Layer "VDD" (solid, remove dead copper, pour order 34): 12.065,11.684 12.065,11.439 12.065,9.779 11.811,9.525 10.287,9.525 9.906,9.906 9.906,11.811 9.906,12.065 9.906,11.684 10.033,11.811 10.287,11.811 10.668,11.811 11.938,11.811
SC on Bottom Layer "SC" (solid, remove dead copper, pour order 6): 8.128,15.367 8.128,14.106 8.128,13.97 8.636,13.716 8.636,9.271 8.382,9.017 6.731,9.017 6.223,8.509 6.223,6.477 5.969,6.223 5.461,6.223 5.207,6.477 5.207,8.509 5.08,8.636 4.572,8.636 4.445,8.763 4.445,9.906 4.318,10.033 3.937,10.414 3.556,10.795 1.651,10.795 1.27,11.176 1.27,12.319 1.651,12.7 3.429,12.7 3.683,12.446 3.683,11.811 4.191,11.303 4.572,11.303 6.35,11.303 6.477,11.43 6.604,11.557 6.604,11.684 6.604,13.589 6.35,13.843 6.35,15.367
SB on Bottom Layer "SB" (solid, remove dead copper, pour order 8): 0.508,13.335 0.762,13.081 0.762,9.271 0.762,9.144 0.381,8.763 -0.381,8.763 -1.143,8.089 -1.778,7.62 -1.778,7.874 -1.778,5.715 -2.54,5.715 -2.54,8.001 -2.54,7.62 -3.81,8.636 -5.755,8.636 -8.084,8.636 -7.783,8.636 -8.412,9.144 -8.412,9.5 -6.987,10.924 -6.609,10.795 -6.987,10.924 -6.191,10.541 -6.096,10.541 -5.969,10.541 -5.334,10.795 -4.699,10.795 -4.318,10.795 -4.191,10.795 -1.651,10.795 -1.143,11.303 -1.143,11.43 -1.143,13.208 -1.016,13.335
SGND on Bottom Layer "SGND" (solid, remove dead copper, pour order 20): 8.076,-6.858 8.128,-6.91 8.128,-10.033 4.953,-10.033 4.953,-6.858 6.477,-6.858 8.076,-6.858 8.128,-6.806
SGND on Bottom Layer "SGND" (solid, remove dead copper, pour order 22): 0.106,-3.81 0.751,-4.456 1.016,-4.72 1.016,-5.207 1.016,-5.334 1.016,-5.461 -0.635,-5.461 -0.889,-5.461 -1.27,-5.08 -2.794,-5.08 -2.921,-4.953 -2.921,-3.937 -2.794,-3.81
VREF on Bottom Layer "VREF" (solid, remove dead copper, pour order 24): 8.636,-6.731 9.525,-6.731 9.652,-6.731 9.779,-6.604 10.668,-6.604 11.557,-5.715 11.811,-5.461 11.811,-4.572 11.811,-4.318 13.208,-4.318 13.208,-2.54 13.081,-2.667 11.684,-2.667 10.414,-2.667 10.414,-3.429 11.176,-3.429 11.176,-4.318 10.414,-4.318 9.779,-4.318 9.652,-4.445 11.303,-4.445 10.668,-4.445 10.541,-4.572 10.668,-4.445 9.652,-4.445 9.525,-4.572 9.525,-5.08 9.525,-6.096 9.398,-6.223 9.144,-6.477 8.636,-6.477
SGND on Bottom Layer "SGND" (solid, remove dead copper, pour order 30): -4.064,6.223 -4.064,2.794 -3.429,2.045 -2.159,2.045 -1.016,2.045 -0.635,1.524 -0.635,-1.905 -1.016,-2.286 -2.667,-2.286 -3.429,-2.286 -4.445,-2.286 -4.572,-2.286 -5.086,-1.778 -5.086,1.657 -5.588,2.413 -5.588,2.54 -5.588,6.731 -4.572,6.731
VDD on Bottom Layer "VDD" (solid, remove dead copper, pour order 50): -4.475,12.528 cw(c-4.344,12.621) -4.475,12.713 cw(c-4.393,12.727) -4.434,12.799 cw(c3.082,2.609) 0,14.89 cw(c0.567,11.653) 0.903,14.923 0.762,13.859 -1.032,13.859 -1.649,13.335 -1.649,11.698 -2.032,11.314 -4.434,11.314
VDD on Bottom Layer "VDD" (solid, remove dead copper, pour order 52): 0.564,14.951 0.514,13.849 0.756,13.849 1.27,13.229 1.27,13.208 1.397,13.208 3.937,13.208 4.064,13.081 4.191,12.954 4.191,11.938 4.318,11.811 4.445,11.811 5.969,11.811 6.096,11.938 6.096,12.065 6.096,13.589 5.715,13.97 5.715,14.732 5.461,14.986 5.429,14.954
SA on Bottom Layer "VDD" (solid, remove dead copper, pour order 54): 10.898,12.606 11.176,12.218 11.684,12.218 11.938,12.218 12.44,11.817 12.44,9.779 12.44,9.525 11.808,8.893 10.795,8.893 10.795,8.636 11.05,8.255 11.05,7.104 11.304,7.104 11.547,6.975 11.547,6.742 11.547,6.477 11.176,6.106 11.176,4.318 11.304,4.19 11.547,4.19 11.808,4.451 11.808,5.969 12.18,6.341 12.944,7.105 14.605,7.105 16.533,5.334 16.533,4.064 16.533,3.516 16.64,2.029 16.891,2.029 17.275,2.413 17.551,3.046 17.908,3.683 18.675,4.572 18.675,4.064 18.675,4.829 18.161,6.341 16.764,5.842 15.623,7.997 15.623,8.255 15.75,8.506 16.004,8.636 16.533,8.907 ccw(c5.448,1.791) 11.304,13.59 11.05,13.59 10.898,13.438
ISENSE on Bottom Layer "ISENSE" (solid, remove dead copper, pour order 56): -2.413,5.461 -2.54,5.461 -2.54,3.81 -2.159,3.429 -0.635,3.429 -0.635,3.683 -0.254,4.064 0.127,4.064 0.381,4.191 0.762,4.572 2.794,5.461 2.921,5.461 5.334,5.461 7.239,4.699 7.366,4.699 7.239,4.699 9.398,2.794 9.779,2.794 10.668,2.794 10.922,2.794 11.176,2.54 11.176,1.524 11.684,0.889 12.827,0.889 12.954,1.016 13.081,1.143 13.208,1.27 13.208,1.651 13.208,1.778 13.97,2.54 14.097,2.667 14.224,2.794 14.478,2.794 14.732,2.794 14.859,2.667 14.859,2.54 15.748,2.54 15.748,2.667 15.748,3.556 15.748,4.699 14.351,6.223 13.716,6.223 13.335,5.842 13.335,3.429 13.335,2.667 13.208,2.54 13.081,2.413 12.827,2.286 11.938,2.286 11.684,2.54 11.684,3.302 10.668,3.302 10.414,3.302 10.16,3.302 9.906,3.302 8.763,4.445 8.763,8.128 8.636,8.255 7.747,8.255 7.493,8.001 7.62,8.128 7.62,6.223 7.239,5.969 4.191,5.969 3.302,6.858 2.921,7.239 1.524,7.239 1.524,7.493 1.524,7.747 0.127,7.747 -0.127,7.493 -0.127,7.366 -0.127,7.239 -0.127,5.715 0,5.588 0,5.461 0,5.207 -0.127,5.08 -0.254,4.953 -0.508,4.826 -0.762,4.953 -1.27,5.461 -2.54,5.461
VDD on Top Layer "VDD" (solid, remove dead copper, pour order 48): -8.608,5.841 -10.325,5.841 -10.526,5.64 -10.526,4.688 -10.225,4.564 -6.86,4.564 -6.614,4.834 -6.614,6.975 -5.969,7.62 -4.572,7.62 -3.938,8.083 -3.938,10.667 -3.386,11.219 -2.032,11.219 -1.553,11.698 8.282,11.75 8.956,11.076 8.956,10.353 10.541,9.49 11.973,9.49 12.118,9.636 12.118,12.582 11.557,12.954 10.922,13.208 10.541,13.335 9.652,12.954 7.258,14.205 7.366,14.86 ccw(c3.811,-386.047) 0.255,14.86 ccw(c17.111,-46.724) -0.844,14.548 ccw(c28.094,-54.931) -3.048,13.589 ccw(c27.706,-30.83) -4.454,12.582 ccw(c30.199,12.04) -4.454,11.521 ccw(c37.743,-32.039) -5.817,10.158 ccw(c-28.696,-34.595) -6.626,10.563 ccw(c-18.194,-7.993) -7.007,10.795 ccw(c42.575,-32.532) -8.357,9.2 ccw(c22.673,48.42) -7.123,8.255 ccw(c2.917,0.416) -8.255,6.535 ccw(c-4.162,4.016)
ISENSE on Top Layer "ISENSE" (solid, remove dead copper, pour order 36): -5.842,6.985 -5.969,6.858 -5.969,5.334 -5.969,4.445 -5.755,4.231 -3.088,4.231 -2.539,4.065 -2.412,3.937 -1.778,3.937 -1.778,3.303 -1.523,3.048 -1.016,3.048 -1.016,3.937 -1.143,4.572 -1.778,5.207 -1.784,6.731 -1.714,6.731 -1.968,6.985
SGND on Top Layer "SGND" (solid, remove dead copper, pour order 16): -10.412,3.935 -10.541,3.806 -10.541,2.794 -10.287,2.667 -8.89,2.667 -8.636,2.413 -8.509,2.286 -8.382,1.905 -8.382,1.27 -8.382,0.889 -6.985,-0.635 -5.716,-0.635 -5.716,0.127 -0.889,0.127 -0.888,1.652 -0.889,1.778 -2.159,3.048 -2.159,3.556 -3.556,3.556 -4.191,3.556 -4.191,6.35 -4.191,3.556 -6.227,3.556 -6.606,3.935 -8.509,3.935
SGND on Top Layer "SGND" (solid, remove dead copper, pour order 18): -1.46,-1.778 -2.413,-1.778 -2.254,-1.778 -2.127,-1.905 -2.127,-2.254 1.524,-5.842 3.302,-5.842 3.619,-6.096 5.016,-6.096 5.779,-5.334 9.144,-5.334 9.271,-5.461 9.277,-5.963 9.144,-6.096 8.255,-6.096 8.255,-9.652 8.001,-9.906 4.318,-9.906 2.917,-8.505 2.917,-6.727 2.667,-6.477 2.095,-6.477 -0.063,-6.477 -0.635,-6.985 -0.889,-7.239 -1.016,-7.366 -1.524,-7.366 -1.524,-7.112 -1.651,-6.985 -2.095,-6.985 -2.667,-6.985 -2.667,-6.341 -2.93,-6.341 -3.048,-6.223 -3.048,-5.842 -3.302,-5.461 -3.683,-5.461 -4.191,-5.461 -4.445,-5.207 -4.445,-3.81 -4.445,-2.921 -4.254,-2.794 -4.254,-1.778 -3.302,-1.778 -3.175,-1.778 -3.048,-1.778 -3.111,-1.778
VREF on Top Layer "VREF" (solid, remove dead copper, pour order 26): -3.683,-5.842 -3.175,-6.477 -3.175,-7.175 -3.175,-8.064 -2.794,-8.445 0.381,-8.445 0.381,-7.556 0.635,-7.302 1.27,-7.302 1.27,-8.572 1.397,-8.7 1.778,-9.08 2.032,-9.08 2.286,-9.08 3.683,-10.477 3.937,-10.477 8.509,-10.477 8.636,-10.351 8.763,-10.223 8.763,-9.716 8.763,-6.985 9.525,-6.223 9.652,-6.096 9.652,-5.969 9.779,-5.842 10.287,-5.696 12.192,-5.696 12.192,-6.604 10.287,-8.191 10.541,-7.938 10.033,-8.445 9.652,-8.826 9.652,-11.239 9.652,-10.541 9.144,-11.049 8.255,-11.684 8.255,-11.747 -3.683,-11.747 -4.572,-10.858 -4.699,-10.731 -4.699,-5.842

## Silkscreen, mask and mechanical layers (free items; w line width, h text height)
Top Overlay:
  text "VDD" at -8.636,4.826 h0.6
  text "GND" at -8.636,2.794 h0.6
  text "BRA" at -8.509,1.016 h0.6
  text "VSP" at -8.636,-1.016 h0.6
  text "DIR" at -8.509,-2.794 h0.6
  text "PWM" at -8.636,-4.953 h0.6
  text "FG" at -8.509,-6.858 h0.6
Bottom Overlay:
  text "C" at 5.842,13.97 h0.51
  text "B" at -5.588,10.287 h0.51
  text "A" at 18.288,5.969 h0.51
Mechanical 1:
  circle w0.203: c4.013,-0.127 r3.9
  lines w0.203: -0.814,-15.486 cw(c4.013,-0.127) -10.855,-6.302 -10.855,7.013 -9.055,6.083 -7.95,8.115 -9.251,8.999 cw(c4.013,-0.127) -6.938,11.675 -6.41,11.147 ccw(c-6.077,11.479) -5.745,11.147 -5.266,11.626 ccw(c-5.598,11.958) -5.266,12.291 -5.693,12.718 cw(c4.013,-0.127) 0.279,15.534 ; -0.814,-15.483 8.85,-15.483 ccw(c4.013,-0.127) 19.343,-5.047 19.343,4.834 ; 0.281,15.532 8.687,15.532 8.344,14.491 9.588,13.97 9.905,14.856 cw(c4.013,-0.127) 17.34,8.906 16.066,8.23 16.066,8.064 16.904,6.439 17.145,6.413 18.484,6.93 cw(c4.013,-0.127) 19.323,4.854 ; 2.692,-15.448 2.692,-14.732 cw(c3.162,-14.732) 3.162,-14.262 4.737,-14.262 cw(c4.737,-14.668) 5.143,-14.668 5.143,-15.41 ccw(c5.182,-15.41) 5.182,-15.448 ; 19.3,1.887 cw(c18.986,2.68) 19.343,3.454
Mechanical 15:
  lines w0.254: 0.717,6.779 cw(c3.937,-0.127) 3.937,7.493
